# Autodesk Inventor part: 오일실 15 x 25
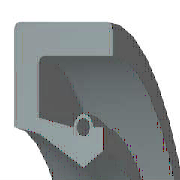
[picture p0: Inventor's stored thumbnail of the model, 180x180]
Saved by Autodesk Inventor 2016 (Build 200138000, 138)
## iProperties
IsCustomPart: 0
Created: 2015-10
Part Number: 오일실 15 x 25
Material: Rubber
Description: 오일-실
Document SubType Name: Modeling
Standard: KS B 2804
Designer: mdu
Standards Organization: KS
Language: ko-KR
Size Designation: S - 15 25 7
Categories: <MemberInstance><Categories><Category DisplayName="샤프트 부품" InternalName="7f7aeb1f-a693-4053-b835-cee3144e0d98" Mnemonic="SHFT"><Category DisplayName="실링" Intern
Density: 0.93 g/cm^3
Appearance: Rubber - Black - Version 1.1
Author: mdu
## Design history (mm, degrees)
revolve "본체" stored, may be unused: angle "d17" = 90 deg
revolve "스프링1" stored, may be unused: angle "d18" = 90 deg
body "Solid1"
sketch "스케치1"
  geometry: L1 (0, 12.5)-(7, 12.5); L2 (7, 12.5)-(7, 11.25); L3 (7, 11.25)-(1.75, 11.25); L4 (0, 12.5)-(0, 9.6); L5 (0, 9.6)-(1.75, 9.25); L6 (1.75, 9.25)-(4.9, 7.5); L7 (4.9, 7.5)-(0, 7.5); L8 (6.3, 8.375)-(6.3, 9.6); L9 (0, 0)-(9.586, 0) reference; L10 (4.9, 7.5)-(6.3, 8.375); L11 (0, 18)-(0, -3) reference; L12 (-1.917, 0)-(11.503, 0) reference; L13 (4.2, 9.6)-(1.75, 10.09); L14 (1.75, 10.09)-(1.75, 11.25); L15 (6.3, 9.6)-(5.6, 9.6); C1 r 0.455 at (4.9, 9.6); A1 r 0.7 centre (4.9, 9.6) between (5.6, 9.6) and (4.2, 9.6)
  constraints: 26 end point, 5 horizontal alignment, 4 perpendicular, 2 centre point, 2 collinear, 2 horizontal, 2 parallel, 2 point on circle, 2 point on line, 2 vertical alignment, 1 coincident
  dimensions: "d0" = 25 diameter of L1 L9 (= SD2); "d1" = 16.75 diameter of L8.start L9 (= ABDM); "d2" = 1.25 distance of L1.end L2.end (computed from SD); "d3" = 0.91 diameter of C1 (= SPDI); "d4" = 1.4 diameter of A1 (= SPDA); "d5" = 15 diameter of L6.end L9 (= NND); "d6" = 18.5 diameter of L5.end L9 (= TKDM); "d7" = 19.2 diameter of L4.end L9 (= HLDM); "d8" = 4.9 distance from line of C1.centre L4 (= SPDST); "d9" = 6.3 distance between parallel lines of L8 L4 (= SDI); "d10" = 7 distance between parallel lines of L2 L4 (= SWDT); "d12" = 1.75 distance between parallel lines of L14 L4 (= SD)
fillet "모깎기1" dims "d11" = 0.3 (= RR)
other parameters: "SD2" = 25 [user parameter; used in 1 equation term], "SWDT" = 7 [user parameter; used in 1 equation term], "RR" = 0.3 [user parameter; used in 1 equation term], "SD" = 1.75 [user parameter; used in 2 equation terms], "NND" = 15 [user parameter; used in 1 equation term], "SPDA" = 1.4 [user parameter; used in 1 equation term], "SPDI" = 0.91 [user parameter; used in 1 equation term], "TKDM" = 18.5 [user parameter; used in 1 equation term], "HLDM" = 19.2 [user parameter; used in 1 equation term], "ABDM" = 16.75 [user parameter; used in 1 equation term], "SDI" = 6.3 [user parameter; used in 1 equation term], "SPDST" = 4.9 [user parameter; used in 1 equation term], "d13" = 0, "d14" = 0, "d15" = 0, "LAB" = 0.35 [user parameter]
